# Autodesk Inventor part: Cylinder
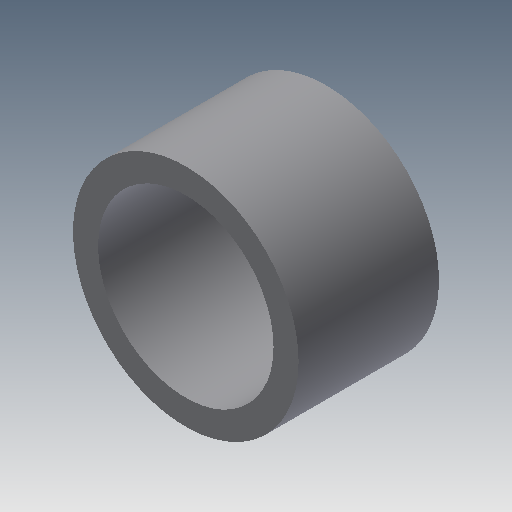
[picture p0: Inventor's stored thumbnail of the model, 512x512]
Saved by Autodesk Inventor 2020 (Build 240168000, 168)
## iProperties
Created: 2010-05
Part Number: Cylinder
Document SubType Name: Modeling
Designer: CADSoft
Density: 1 g/cm^3
Material: Generic
Appearance: Default
Author: CADSoft
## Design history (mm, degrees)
sketch "Sketch1"
  geometry: C1 r 87.5 at (0, 0); C2 r 112.5 at (0, 0); 1 further point
  constraints: 2 centre point, 2 coincident
  dimensions: "d0" = 175 diameter of C1; "d1" = 225 diameter of C2
extrude "Extrusion1" new body sketch "Sketch1" distance "d2" = 140; taper "d3" = 0 deg
body "Solid1"
